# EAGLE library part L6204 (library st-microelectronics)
DUAL DMOS FULL BRIDGE DRIVER
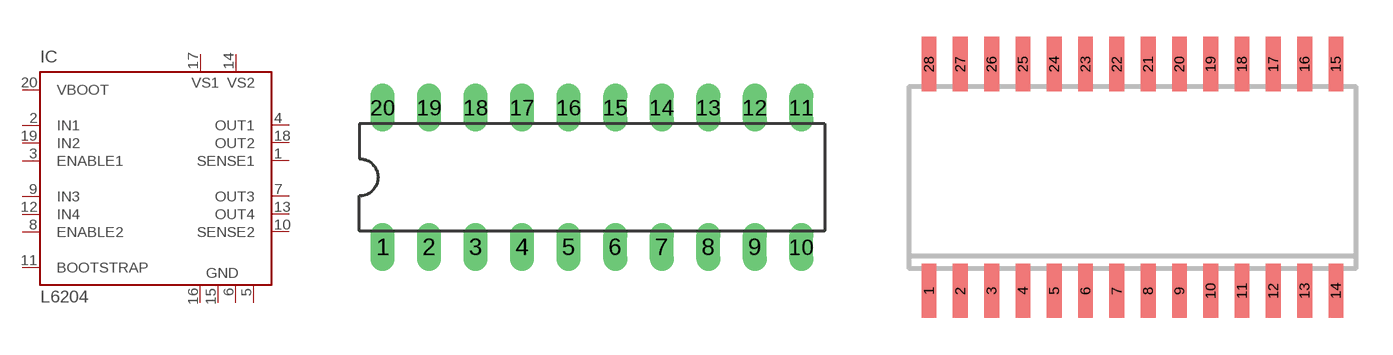
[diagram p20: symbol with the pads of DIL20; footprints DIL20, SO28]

Designator prefix IC

## L6204 (MPN: E-L6204; OC_FARNELL: 1564367; OC_NEWARK: 56P7372)  [DIL20]
1  SENSE1  in
2  IN1  in
3  ENABLE1  in
4  OUT1  out
5  GND  pwr
6  GND  pwr
7  OUT3  out
8  ENABLE2  in
9  IN3  in
10  SENSE2  in
11  BOOTSTRAP  in
12  IN4  in
13  OUT4  out
14  VS2  pwr
15  GND  pwr
16  GND  pwr
17  VS1  pwr
18  OUT2  out
19  IN2  in
20  VBOOT  in

## L6204D (MPN: L6204D; OC_FARNELL: unknown; OC_NEWARK: 37M3485)  [SO28]
1  SENSE1  in
2  IN1  in
3  ENABLE1  in
6  OUT1  out
7  GND  pwr
8  GND  pwr
9  OUT3  out
12  ENABLE2  in
13  IN3  in
14  SENSE2  in
15  BOOTSTRAP  in
16  IN4  in
17  OUT4  out
20  VS2  pwr
21  GND  pwr
22  GND  pwr
23  VS1  pwr
26  OUT2  out
27  IN2  in
28  VBOOT  in

## Footprint DIL20 (pad centres in mm)
Dual In Line Package
drill 0.813 long: 1 -11.43,-3.81; 2 -8.89,-3.81; 3 -6.35,-3.81; 4 -3.81,-3.81; 5 -1.27,-3.81; 6 1.27,-3.81; 7 3.81,-3.81; 8 6.35,-3.81; 9 8.89,-3.81; 10 11.43,-3.81; 11 11.43,3.81; 12 8.89,3.81; 13 6.35,3.81; 14 3.81,3.81; 15 1.27,3.81; 16 -1.27,3.81; 17 -3.81,3.81; 18 -6.35,3.81; 19 -8.89,3.81; 20 -11.43,3.81

## Footprint SO28 (pad centres in mm)
SMALL OUTLINE INTEGRATED CIRCUIT wide body 7.5 mm/JEDEC MO-119AB
smd 0.6 x 2.2: 1 -8.255,-4.6; 2 -6.985,-4.6; 3 -5.715,-4.6; 4 -4.445,-4.6; 5 -3.175,-4.6; 6 -1.905,-4.6; 7 -0.635,-4.6; 8 0.635,-4.6; 9 1.905,-4.6; 10 3.175,-4.6; 11 4.445,-4.6; 12 5.715,-4.6; 13 6.985,-4.6; 14 8.255,-4.6; 15 8.255,4.6; 16 6.985,4.6; 17 5.715,4.6; 18 4.445,4.6; 19 3.175,4.6; 20 1.905,4.6; 21 0.635,4.6; 22 -0.635,4.6; 23 -1.905,4.6; 24 -3.175,4.6; 25 -4.445,4.6; 26 -5.715,4.6; 27 -6.985,4.6; 28 -8.255,4.6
